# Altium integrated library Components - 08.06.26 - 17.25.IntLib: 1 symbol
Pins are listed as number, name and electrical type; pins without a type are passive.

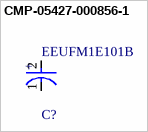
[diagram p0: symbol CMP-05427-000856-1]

## CMP-05427-000856-1
designator C?, comment EEUFM1E101B
Aluminum Electrolytic Capacitors (Radial Lead Type) 100uF ±20% 25V; Lead Diameter: 0.5mm; Polarity: Polar; Ripple Current: 455mA; Impedance: 130mR; Life (Hours): 2000Hour
footprint FP-RAD-TH-D_6_3_0_5-L_11-MFG
pins: 1 C, 2 A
